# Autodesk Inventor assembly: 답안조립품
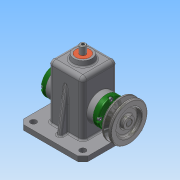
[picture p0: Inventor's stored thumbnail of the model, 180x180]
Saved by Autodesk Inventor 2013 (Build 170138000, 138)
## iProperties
Created: 2016-02
Part Number: 답안조립품
Document SubType Name: Assembly
Designer: Administrator
Author: Administrator
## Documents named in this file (16)
- C:\Users\Administrator\Desktop\답안조립품.iam
- C:\Users\Administrator\Desktop\본체.ipt
- C:\Users\Administrator\Desktop\460212V1013\편심축.ipt
- C:\Users\Administrator\Desktop\460212V1013\키 4 x 4 x 10.ipt
- C:\Users\Administrator\Desktop\460212V1013\베어링 12 x 32 x 10.ipt
- C:\Users\Administrator\Desktop\460212V1013\링크.ipt
- C:\Users\Administrator\Desktop\460212V1013\뒤커버.ipt
- C:\Users\Administrator\Desktop\460212V1013\고정핀 1.2 x 10.ipt
- C:\Users\Administrator\Desktop\460212V1013\핀 5 x 18.ipt
- C:\Users\Administrator\Desktop\460212V1013\부시.ipt
- C:\Users\Administrator\Desktop\460212V1013\앞커버.ipt
- C:\Users\Administrator\Desktop\460212V1013\오일실 12 25 7.ipt
- C:\Users\Administrator\Desktop\460212V1013\슬라이드.ipt
- C:\Users\Administrator\Desktop\460212V1013\볼트 M4 x 12.ipt
- C:\Users\Administrator\Desktop\460212V1013\멈춤나사 M3x8.ipt
- C:\Users\Administrator\Desktop\460212V1013\V벨트풀리.ipt
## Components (11 placed, 4 different names)
1. 핀 5 x 18:1 — 각도:4
2. ISO 4762 M4 x 12:1
3. ISO 4762 M4 x 12:2
4. ISO 4762 M4 x 12:3
5. ISO 4762 M4 x 12:4
6. ISO 4762 M4 x 12:5
7. ISO 4762 M4 x 12:6
8. ISO 4762 M4 x 12:7
9. ISO 4762 M4 x 12:8
10. V벨트풀리:1 — 각도:3, 각도:5
11. 고정핀 1.2 x 10:1 — 각도:4, 각도:5
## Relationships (3: Angle 3)
- 각도:3 [Angle]: V벨트풀리:1
- 각도:4 [Angle]: 핀 5 x 18:1 ↔ 고정핀 1.2 x 10:1
- 각도:5 [Angle]: V벨트풀리:1 ↔ 고정핀 1.2 x 10:1
